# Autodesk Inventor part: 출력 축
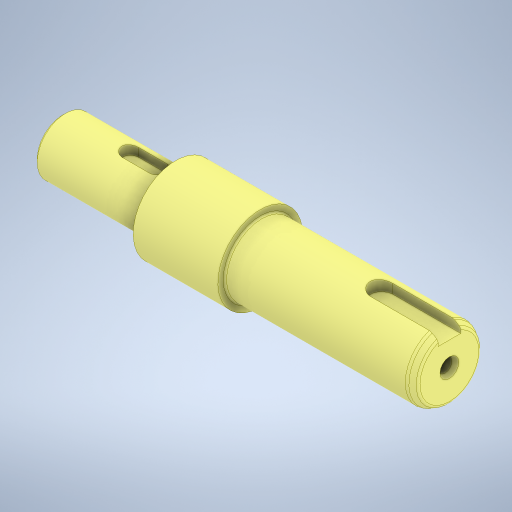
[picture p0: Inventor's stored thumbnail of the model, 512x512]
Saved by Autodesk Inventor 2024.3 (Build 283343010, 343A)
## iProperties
Created: 2025-11
Part Number: 출력 축
Material: 강철, 탄소
Document SubType Name: Modeling
Designer: PC2-15
Density: 7.85 g/cm^3
Appearance: 기본값
Author: jhkim
Sending System: Autodesk Inventor 2026
Preprocessor: ST-DEVELOPER v20.1
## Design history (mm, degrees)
node "출력 축1"
node "솔리드2"
node "솔리드1"
